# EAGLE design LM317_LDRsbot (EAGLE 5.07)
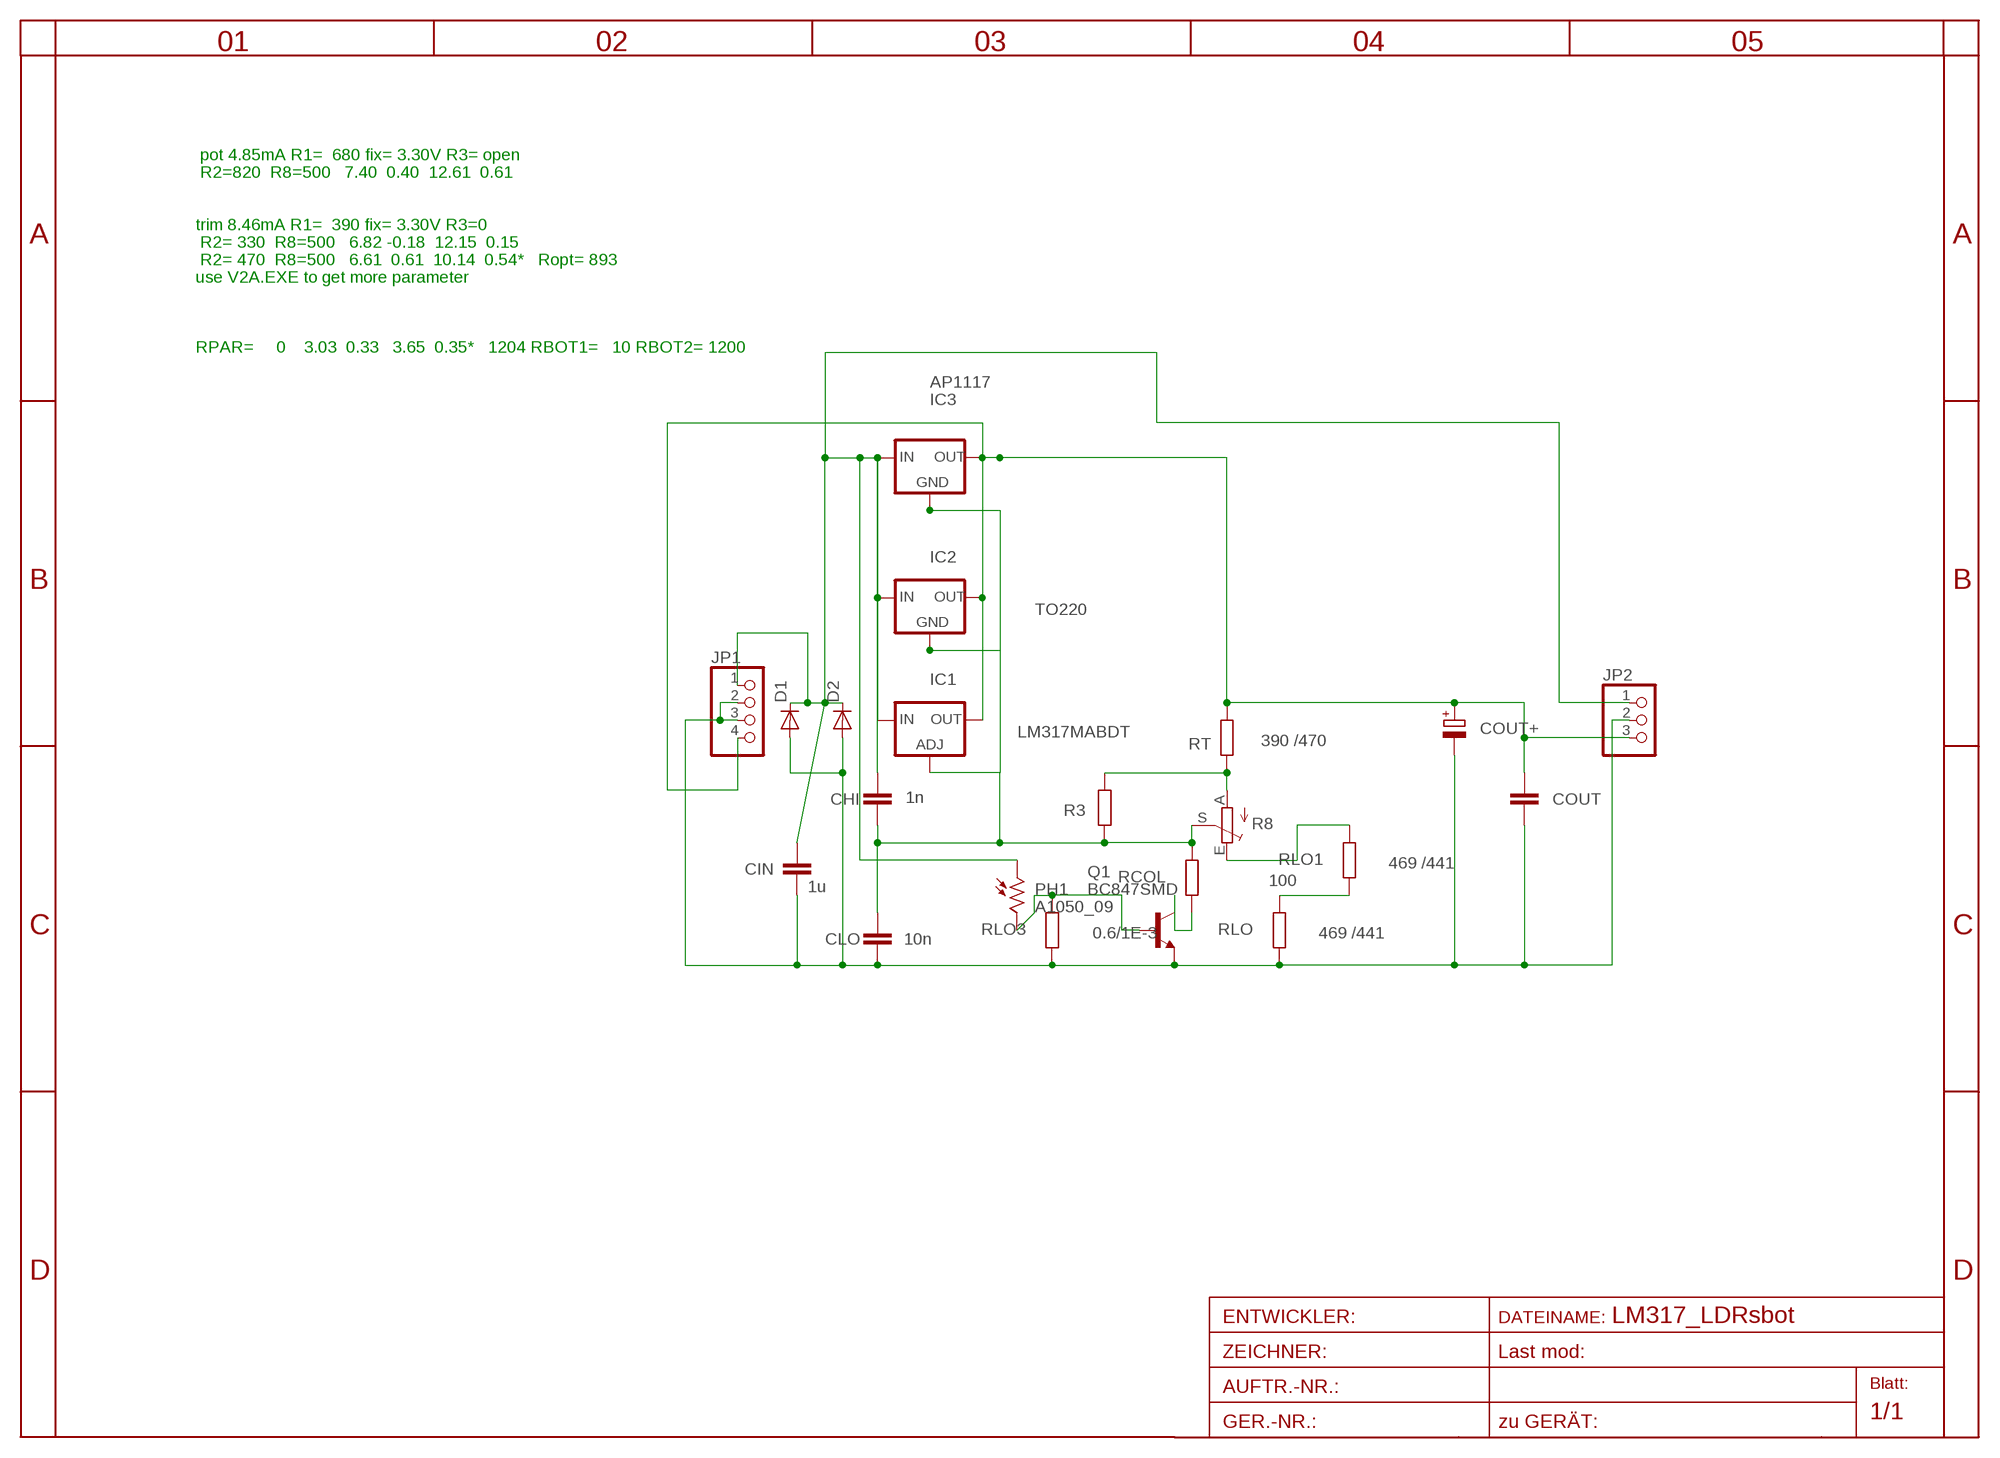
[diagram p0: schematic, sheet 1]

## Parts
CHI  1n  C-EUC0805  [C0805]
CIN  1u  C-EUC1206  [C1206]
CLO  10n  C-EUC0805  [C0805]
COUT  C-EUC1206  [C1206]
COUT+  CPOL-EUE2.5-6  [E2,5-6]
D1  DIODE-MINIMELF  [MINIMELF]
D2  DIODE-MINIMELF  [MINIMELF]
IC1  LM317MABDT  [DPACK]
IC2  TO220  78XXS  [78XXS]
IC3  AP1117  [SOT223]
JP1  PINHD-1X4  [1X04]
JP2  PINHD-1X3  [1X03]
PH1  A1050_09  [T0-46-A10XX]
Q1  BC847SMD  [SOT23]
R3  R-EU_R0805  [R0805]
R8  TRIM_EU-RAND160  [RANDL]
RCOL  100  R-EU_R0805  [R0805]
RLO  469 /441  R-EU_R0805  [R0805]
RLO1  469 /441  R-EU_R0805  [R0805]
RLO3  0.6/1E-3  R-EU_R0805  [R0805]
RT  390 /470  R-EU_R0805  [R0805]

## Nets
GND: CIN.2 CLO.2 COUT+.- COUT.2 D1.A D2.A JP1.2 JP1.3 JP2.2 Q1.2(E) RLO3.1 RLO.1
IN: CHI.1 CIN.1 D1.C D2.C IC1.3(IN) IC2.IN IC3.3(IN) JP1.1 JP2.1 PH1.1
N$1: R8.E RLO1.2
N$2: RLO1.1 RLO.2
N$3: Q1.3(C) RCOL.1
N$4: CHI.2 CLO.1 IC1.1(ADJ) IC2.GND IC3.1(GND) R3.1 R8.S RCOL.2
N$5: PH1.2 Q1.1(B) RLO3.2
N$7: R3.2 R8.A RT.1
OUT: COUT+.+ COUT.1 IC1.4(OUT) IC2.OUT IC3.2(OUT) IC3.4(TAB) JP1.4 JP2.3 RT.2

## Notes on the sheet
- pot 4.85mA R1=  680 fix= 3.30V R3= open
- R2=820  R8=500   7.40  0.40  12.61  0.61
- trim 8.46mA R1=  390 fix= 3.30V R3=0
- R2= 330  R8=500   6.82 -0.18  12.15  0.15
- R2= 470  R8=500   6.61  0.61  10.14  0.54*   Ropt= 893
- use V2A.EXE to get more parameter
- RPAR=     0    3.03  0.33   3.65  0.35*   1204 RBOT1=   10 RBOT2= 1200

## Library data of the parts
CHI CIN CLO COUT = rcl:C-EU: CAPACITOR, European symbol
COUT+ = rcl:CPOL-EU: POLARIZED CAPACITOR, European symbol
D1 D2 = diode-1:DIODE-: DIODE
IC1 = v-reg:LM317?*: 500 mA Adjustable Output Positive Voltage Regulator Source: http://www.onsemi.co.jp .. LM317M-D.PDF
IC2 = v-reg:78XXS: VOLTAGE REGULATOR
IC3 = v-reg:AP1117
JP1 = pinhead:PINHD-1X4: PIN HEADER
JP2 = pinhead:PINHD-1X3: PIN HEADER
PH1 = photo-elements:A10: Sensor Robust Light Sensing Applications
Q1 = transistor-npn:BC847*: NPN Transistor
R3 RCOL RLO RLO1 RLO3 RT = rcl:R-EU_: RESISTOR, European symbol
R8 = pot:TRIM_EU-: POTENTIOMETER

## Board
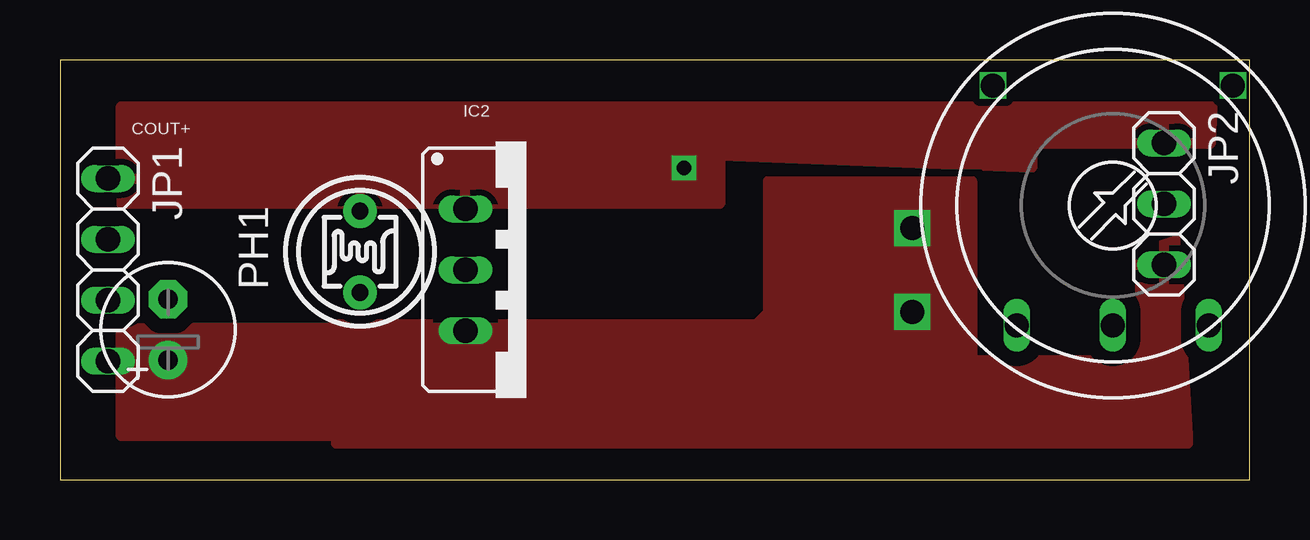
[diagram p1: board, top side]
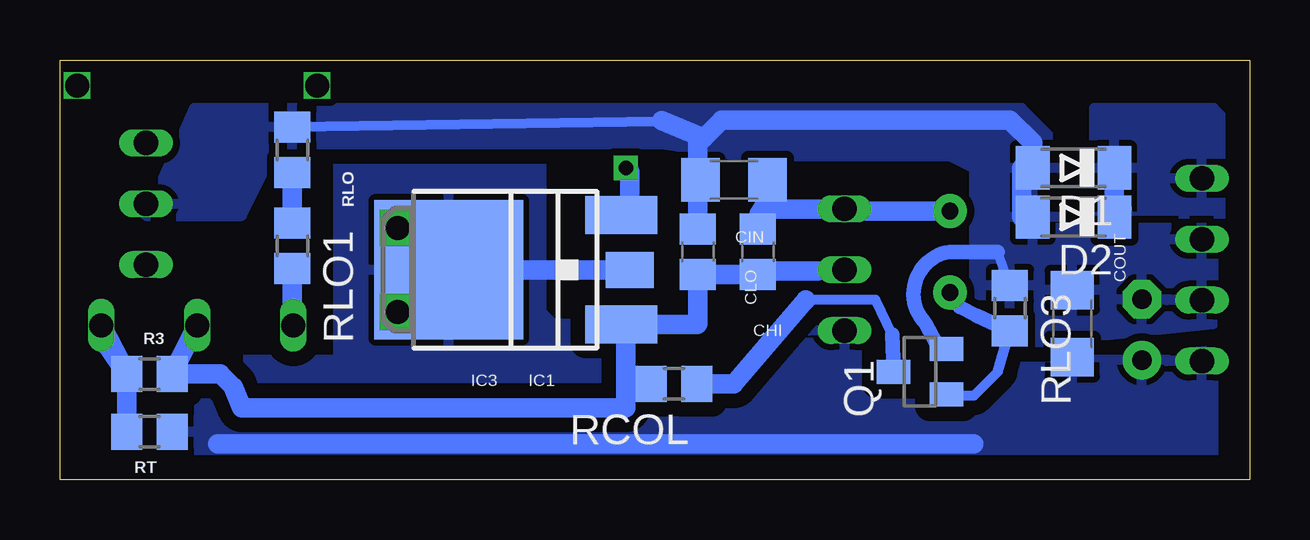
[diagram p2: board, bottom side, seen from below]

Size 49.58 x 17.5 mm. Coordinates in mm from the lower left corner, seen from the top.
Outline: 0,0 49.58,0 49.58,17.5 0,17.5 0,0
Copper layers (1*16): Top 0.035mm / dielectric 1.5mm / Bottom 0.035mm
Design rules "default": minimum track width 10mil, minimum drill 20mil, track to track 8mil, track to pad 8mil, pad to pad 8mil, via to via 8mil, smd to smd 8mil, copper to edge 40mil, drill to drill 8mil, minimum pad ring 1mil, minimum via ring 8mil, stop-mask expansion 4mil, vias tented up to drill 0mil, thermal gap 10mil

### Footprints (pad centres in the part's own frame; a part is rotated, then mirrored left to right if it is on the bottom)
C0805 = smd 1.3 x 1.5: 1 -0.95,0; 2 0.95,0
C1206 = smd 1.6 x 1.8: 1 -1.4,0; 2 1.4,0
E2,5-6 = drill 0.8 pad 1.6 round: + -1.27,0 | drill 0.8 pad 1.6 octagon: - 1.27,0
MINIMELF = smd 1.4 x 1.8: A 1.7,0; C -1.7,0
DPACK = smd 1.6 x 3: 1 -2.28,-4.8; 3 2.28,-4.8 | smd 5.8 x 6.2: 4 0,2.38
78XXS = drill 1.016 long: GND 0,-2.54; IN -2.54,-2.54; OUT 2.54,-2.54
SOT223 = smd 1.5 x 2: 1 -2.3,-3.15; 2 0,-3.15; 3 2.3,-3.15 | smd 3.8 x 2: 4 0,3.15
1X04 = drill 1.016 long: 1 -3.81,0; 2 -1.27,0; 3 1.27,0; 4 3.81,0
1X03 = drill 1.016 long: 1 -2.54,0; 2 0,0; 3 2.54,0
T0-46-A10XX = drill 0.7 pad 1.4 round: 1 -1.7,0; 2 1.7,0
SOT23 = smd 1 x 1.4: 1 -0.95,-1.1; 2 0.95,-1.1; 3 0,1.1
R0805 = smd 1.3 x 1.5: 1 -0.95,0; 2 0.95,0
RANDL = drill 1 long: A -4,5; E 4,5; S 0,5 | drill 1 square: P$1 -5,-5; P$2 5,-5

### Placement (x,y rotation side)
CHI  20.5,9.5 270 bottom
CIN  21.5,12.5 180 bottom
CLO  23,9.5 90 bottom
COUT  7.4,6.5 90 bottom
COUT+  4.5,6.25 90 top
D1  7.35,13 180 bottom
D2  7.35,10.95 180 bottom
IC1  31,8.75 90 bottom
IC2  19.43,8.75 270 top
IC3  29,8.75 90 bottom
JP1  2,8.75 270 top
JP2  46,11.5 270 top
PH1  12.5,9.5 270 top
Q1  13.75,4.5 90 bottom
R3  45.85,4.4 180 bottom
R8  43.87,11.43 180 top
RCOL  24,4 180 bottom
RLO  39.9,13.75 270 bottom
RLO1  39.9,9.75 270 bottom
RLO3  10,7.15 270 bottom
RT  45.85,2 0 bottom

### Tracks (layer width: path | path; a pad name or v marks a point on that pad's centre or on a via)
GND
  Bottom 0.406: RLO.1 24.56,14.92 24.51,14.97 | 12.95,5.45 Q1.2 | RLO3.1 10.5,9.5
  Bottom 0.61: 12.95,5.45 13.5,6.5 arc127 12.5,9.5 10.5,9.5
  Bottom 0.813: 23,12.6 CLO.2 | D2.A 9.5,10.95 9.5,13 D1.A 9.05,14.05 10,15 22,15 22.75,14.25 | 22.75,14.25 23,14 23,12.6 | 23,12.6 CIN.2 | 22.75,14.25 24.51,14.97
  pour Bottom (isolate 0.305): 1.5,10.5 8,10.5 8,14 9.5,15.5 44,15.5 46,11 42,11 41,13 41,14 24.5,14 21.6,13.55 20.5,13.5 12.5,13.5 11.5,13 11.5,8 11,5.5 1.5,6.5
IN  (via drill 0.6)
  Bottom 0.406: IC1.3 25.85,11.03 IC3.3 | 19.81,11.29 20.2,11.5 | 16.8,11.2 IC2.IN
  Bottom 0.813: CIN.1 20.2,11.5 20.45,11.1 CHI.1 | 5.31,11.29 D2.C D1.C | IC3.3 25.85,12.85 v26,13 | IC2.IN 19.81,11.29 | PH1.1 16.8,11.2
  pour Top (isolate 0.305, rank 2): 2.54,15.56 48,15.56 48,15.5 47.94,14 40.5,14 40.5,13 27.5,13.5 27.5,11.5 2.54,11.5
  pour Bottom (isolate 0.305, rank 2): 1,10.5 1,15 1.5,15.5 6.5,15.5 6.5,11.5 5.5,10 1.5,10
N$1
  Bottom 0.813: RLO1.2 39.9,6.46 R8.E
N$2
  Bottom 0.813: RLO1.1 RLO.2
N$3
  Bottom 0.406: 14.9,6.05 15.6,7.5 18.5,7.5
  Bottom 0.61: Q1.3 14.9,6.05
  Bottom 0.813: 18.5,7.5 21.5,4 RCOL.1
N$4
  Bottom 0.406: IC1.1 25.85,6.47 IC3.1 | IC2.GND 17.75,8.75 18,8.7 | 19.95,8.7 CHI.2 | 26,4 RCOL.2
  Bottom 0.813: CHI.2 CLO.1 23,6.5 23.03,6.47 IC1.1 | IC3.1 26,6.3 26,4 26,3 42,3 42.37,3.87 42.9,4.4 R3.1 43.9,6.4 R8.S | 18,8.7 19.95,8.7
N$5
  Bottom 0.406: PH1.2 12.5,7.5 12.1,7.2 | RLO3.2 10.5,4.5 11.5,3.5 12.6,3.5 Q1.1
  Bottom 0.61: 12.1,7.2 11.4,6.85 RLO3.2
N$7
  Bottom 0.813: R3.2 47.84,6.4 R8.A | R3.2 47.7,5.72 | RT.1 R3.2
OUT  (via drill 1)
  Bottom 0.406: IC1.4 35.5,8.75 v35.5,7
  Bottom 0.813: IC1.4 33,8.37 32.53,8.37 IC3.4 IC3.2 | 11.5,1.5 43,1.5
  other vias: 35.5,10.5
  pour Top (isolate 0.61, no thermals): 2.54,6.35 24.51,6.35 24.51,1.81 2.54,1.81
  pour Bottom (isolate 0.61, rank 2): 29.5,14 38,14 38,5 44.5,5 44.5,0.5 1.5,0.5 1.5,6.5 29,6.5 29.5,7
  pour Top (isolate 0.61): 29.5,12.45 38,12.45 38,5 45,5 45,9.5 46.5,10 47,1.5 11.5,1.5 11.5,6.5 29,6.5 29.5,7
